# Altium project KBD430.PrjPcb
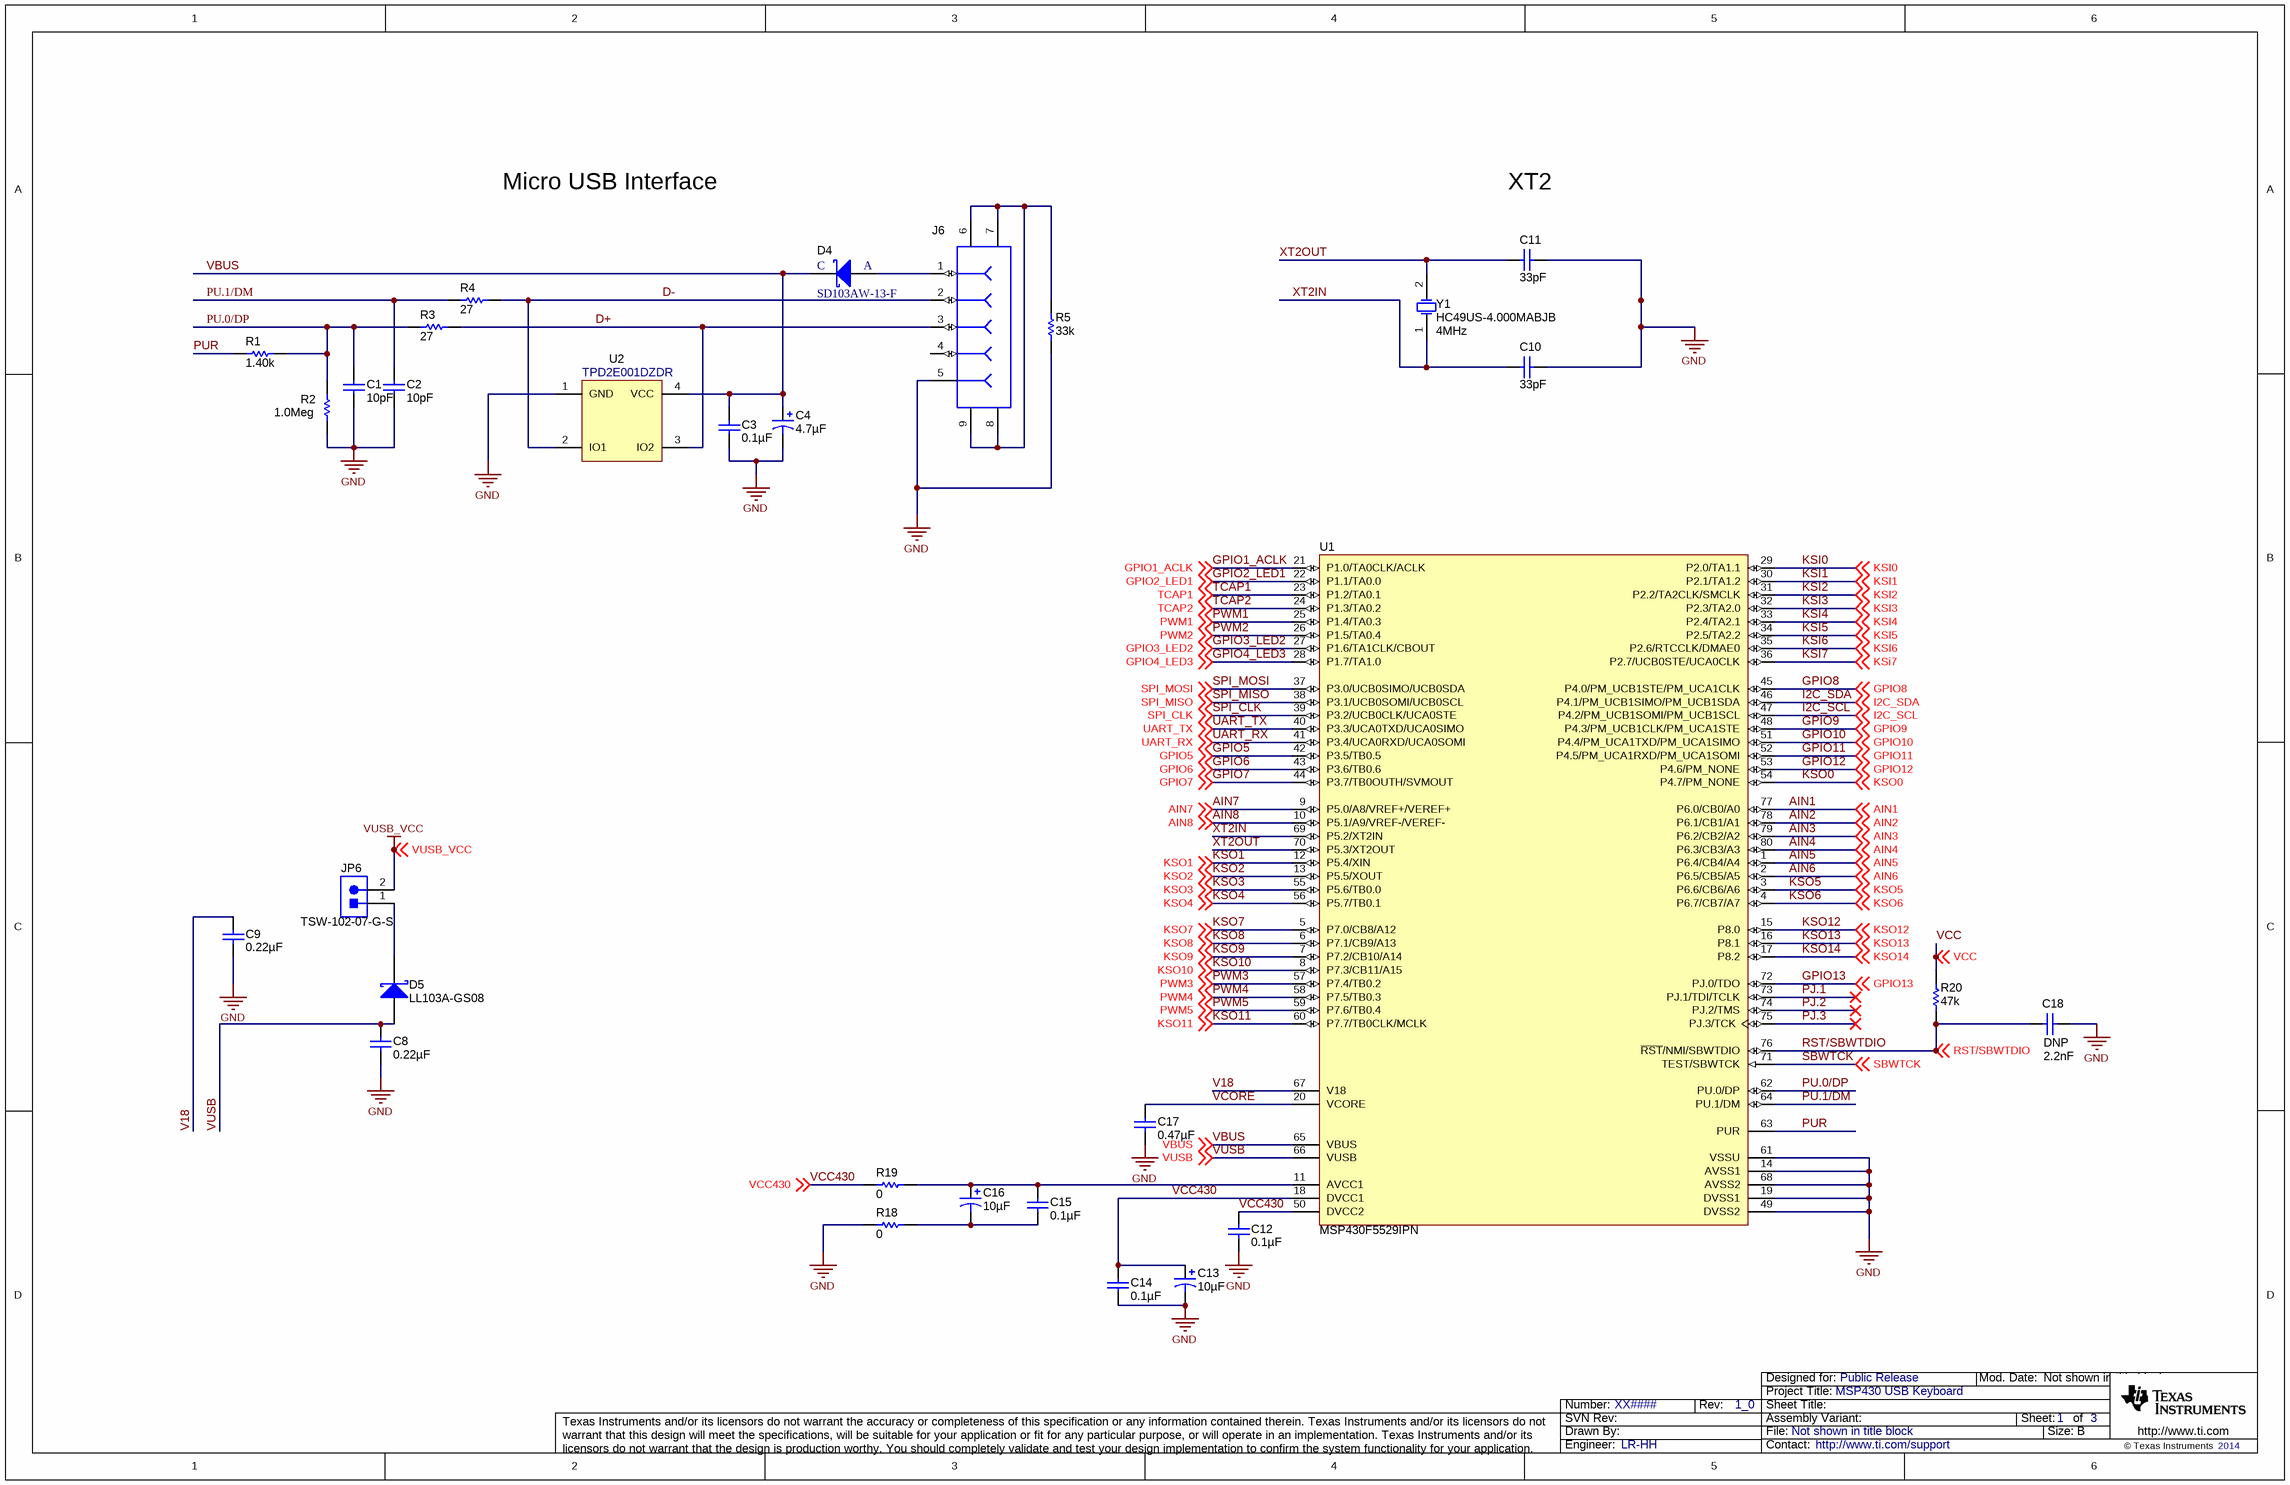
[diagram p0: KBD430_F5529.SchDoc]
CopyrightYear: 2014; PCB_Layout: Hayden Hast; PCB_Rev: 1.0; PRJ_Customer: Public Release; PRJ_Engineer: LR-HH; PRJ_Number: XX####; PRJ_Title: MSP430 USB Keyboard; Project Title: MSP430 USB Keyboard; SCH_Rev: 1_0; TechSupport: http://www.ti.com/support
3 sheets, 72 parts. Net scope: global (net labels, ports and power ports of the same name join across sheets).
Board file: KBD430.PcbDoc
Sheets:
  KBD430_F5529.SchDoc
  KBD430_Shared.SchDoc
  KBD430_G2xx4.SchDoc

## Sheet KBD430_F5529.SchDoc
size 431 x 279 mm; Date: Not shown in title block; ApprovedBy: Not shown in title block; CheckedBy: Not shown in title block; Author: Not shown in title block; CompanyName: Not shown in title block; Engineer: Not shown in title block; Organization: Not shown in title block; Address1: Not shown in title block; Address2: Not shown in title block; Address3: Not shown in title block; Address4: Not shown in title block; DocumentNumber: 1; Revision: Use project parameter SCH_Rev; SheetNumber: 1; SheetTotal: 3; PageSetup: Record=PageOptions|CenterHorizontal=True|CenterVertical=True|PrintScale=0.62|XCorrection=1.00|YCorrection=1.00|PrintKind=0|BorderSize=5000000|LeftOffset=0|BottomOffset=0|Orientation=2|PaperLength=1000|PaperWidth=1000|Scale=100|PaperSource=15|PrintQuality=600|MediaType=1|DitherType=10|PaperKind=Letter (8.5 x 11")|PrintScaleMode=1

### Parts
C1  10pF  [0603]
C2  10pF  [0603]
C3  ValueDisplayed: 0.1µF  [0603]  (hidden comment: 0.1uF)
C4  4.7µF  [3216-18]
C8  ValueDisplayed: 0.22µF  [0603]  (hidden comment: 0.22uF)
C9  ValueDisplayed: 0.22µF  [0603]  (hidden comment: 0.22uF)
C10  33pF  [0603]
C11  33pF  [0603]
C12  ValueDisplayed: 0.1µF  [0603]  (hidden comment: 0.1uF)
C13  ValueDisplayed: 10µF  [3216-18]  (hidden comment: 10uF)
C14  ValueDisplayed: 0.1µF  [0603]  (hidden comment: 0.1uF)
C15  ValueDisplayed: 0.1µF  [0603]  (hidden comment: 0.1uF)
C16  ValueDisplayed: 10µF  [3216-18]  (hidden comment: 10uF)
C17  ValueDisplayed: 0.47µF  [0603]  (hidden comment: 0.47uF)
C18  DNP  ValueDisplayed: 2.2nF  [0603]
D4  SD103AW-13-F  [D_SOD123]
D5  LL103A-GS08  [SOD-80]
J6  ZX62D-AB-5P8  [USB-ZX62D-AB-5P8_REVISED]  (value not drawn)
JP6  TSW-102-07-G-S  [TSW-102-07-G-S]
R1  1.40k  [0603]
R2  1.0Meg  [0603]
R3  27  [0603]
R4  27  [0603]
R5  33k  [0603]
R18  0  [0603]
R19  0  [0603]
R20  47k  [0603]
U1  MSP430F5529IPN  [PN0080A_L]
U2  TPD2E001DZDR  [DZD]
Y1  HC49US-4.000MABJB  Frequency: 4MHz  [Auris_HC49USSMD]

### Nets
GND: C1.2 C2.2 C3.2 C4.2(-) C8.2 C9.2 C10.1 C11.1 C12.2 C13.2(-) C14.2 C17.2 C18.2 J6.5 R2.1 R5.1 R18.1 U1.14(AVSS1) U1.19(DVSS1) U1.49(DVSS2) U1.61(VSSU) U1.68(AVSS2) U2.1(GND)
VCC: R20.2 ; off-sheet VCC
VUSB_VCC: JP6.2 ; off-sheet VUSB_VCC
AIN1: U1.77(P6.0/CB0/A0) ; off-sheet AIN1
AIN2: U1.78(P6.1/CB1/A1) ; off-sheet AIN2
AIN3: U1.79(P6.2/CB2/A2) ; off-sheet AIN3
AIN4: U1.80(P6.3/CB3/A3) ; off-sheet AIN4
AIN5: U1.1(P6.4/CB4/A4) ; off-sheet AIN5
AIN6: U1.2(P6.5/CB5/A5) ; off-sheet AIN6
AIN7: U1.9(P5.0/A8/VREF+/VEREF+) ; off-sheet AIN7
AIN8: U1.10(P5.1/A9/VREF-/VEREF-) ; off-sheet AIN8
D+: J6.3 R3.2 U2.3(IO2)
D-: J6.2 R4.2 U2.2(IO1)
GPIO1_ACLK: U1.21(P1.0/TA0CLK/ACLK) ; off-sheet GPIO1_ACLK
GPIO2_LED1: U1.22(P1.1/TA0.0) ; off-sheet GPIO2_LED1
GPIO3_LED2: U1.27(P1.6/TA1CLK/CBOUT) ; off-sheet GPIO3_LED2
GPIO4_LED3: U1.28(P1.7/TA1.0) ; off-sheet GPIO4_LED3
GPIO5: U1.42(P3.5/TB0.5) ; off-sheet GPIO5
GPIO6: U1.43(P3.6/TB0.6) ; off-sheet GPIO6
GPIO7: U1.44(P3.7/TB0OUTH/SVMOUT) ; off-sheet GPIO7
GPIO8: U1.45(P4.0/PM_UCB1STE/PM_UCA1CLK) ; off-sheet GPIO8
GPIO9: U1.48(P4.3/PM_UCB1CLK/PM_UCA1STE) ; off-sheet GPIO9
GPIO10: U1.51(P4.4/PM_UCA1TXD/PM_UCA1SIMO) ; off-sheet GPIO10
GPIO11: U1.52(P4.5/PM_UCA1RXD/PM_UCA1SOMI) ; off-sheet GPIO11
GPIO12: U1.53(P4.6/PM_NONE) ; off-sheet GPIO12
GPIO13: U1.72(PJ.0/TDO) ; off-sheet GPIO13
I2C_SCL: U1.47(P4.2/PM_UCB1SOMI/PM_UCB1SCL) ; off-sheet I2C_SCL
I2C_SDA: U1.46(P4.1/PM_UCB1SIMO/PM_UCB1SDA) ; off-sheet I2C_SDA
KSI0: U1.29(P2.0/TA1.1) ; off-sheet KSI0
KSI1: U1.30(P2.1/TA1.2) ; off-sheet KSI1
KSI2: U1.31(P2.2/TA2CLK/SMCLK) ; off-sheet KSI2
KSI3: U1.32(P2.3/TA2.0) ; off-sheet KSI3
KSI4: U1.33(P2.4/TA2.1) ; off-sheet KSI4
KSI5: U1.34(P2.5/TA2.2) ; off-sheet KSI5
KSI6: U1.35(P2.6/RTCCLK/DMAE0) ; off-sheet KSI6
KSI7: U1.36(P2.7/UCB0STE/UCA0CLK) ; off-sheet KSi7
KSO0: U1.54(P4.7/PM_NONE) ; off-sheet KSO0
KSO1: U1.12(P5.4/XIN) ; off-sheet KSO1
KSO2: U1.13(P5.5/XOUT) ; off-sheet KSO2
KSO3: U1.55(P5.6/TB0.0) ; off-sheet KSO3
KSO4: U1.56(P5.7/TB0.1) ; off-sheet KSO4
KSO5: U1.3(P6.6/CB6/A6) ; off-sheet KSO5
KSO6: U1.4(P6.7/CB7/A7) ; off-sheet KSO6
KSO7: U1.5(P7.0/CB8/A12) ; off-sheet KSO7
KSO8: U1.6(P7.1/CB9/A13) ; off-sheet KSO8
KSO9: U1.7(P7.2/CB10/A14) ; off-sheet KSO9
KSO10: U1.8(P7.3/CB11/A15) ; off-sheet KSO10
KSO11: U1.60(P7.7/TB0CLK/MCLK) ; off-sheet KSO11
KSO12: U1.15(P8.0) ; off-sheet KSO12
KSO13: U1.16(P8.1) ; off-sheet KSO13
KSO14: U1.17(P8.2) ; off-sheet KSO14
PJ.1: U1.73(PJ.1/TDI/TCLK)
PJ.2: U1.74(PJ.2/TMS)
PJ.3: U1.75(PJ.3/TCK)
PU.0/DP: C1.1 R1.2 R2.2 R3.1 U1.62(PU.0/DP)
PU.1/DM: C2.1 R4.1 U1.64(PU.1/DM)
PUR: R1.1 U1.63(PUR)
PWM1: U1.25(P1.4/TA0.3) ; off-sheet PWM1
PWM2: U1.26(P1.5/TA0.4) ; off-sheet PWM2
PWM3: U1.57(P7.4/TB0.2) ; off-sheet PWM3
PWM4: U1.58(P7.5/TB0.3) ; off-sheet PWM4
PWM5: U1.59(P7.6/TB0.4) ; off-sheet PWM5
RST/SBWTDIO: C18.1 R20.1 U1.76(~{RST}/NMI/SBWTDIO) ; off-sheet RST/SBWTDIO
SBWTCK: U1.71(TEST/SBWTCK) ; off-sheet SBWTCK
SPI_CLK: U1.39(P3.2/UCB0CLK/UCA0STE) ; off-sheet SPI_CLK
SPI_MISO: U1.38(P3.1/UCB0SOMI/UCB0SCL) ; off-sheet SPI_MISO
SPI_MOSI: U1.37(P3.0/UCB0SIMO/UCB0SDA) ; off-sheet SPI_MOSI
TCAP1: U1.23(P1.2/TA0.1) ; off-sheet TCAP1
TCAP2: U1.24(P1.3/TA0.2) ; off-sheet TCAP2
UART_RX: U1.41(P3.4/UCA0RXD/UCA0SOMI) ; off-sheet UART_RX
UART_TX: U1.40(P3.3/UCA0TXD/UCA0SIMO) ; off-sheet UART_TX
V18: C9.1 U1.67(V18)
VBUS: C3.1 C4.1(+) D4.1 U1.65(VBUS) U2.4(VCC) ; off-sheet VBUS
VCC430: C12.1 C13.1(+) C14.1 R19.1 U1.18(DVCC1) U1.50(DVCC2) ; off-sheet VCC430
VCORE: C17.1 U1.20(VCORE)
VUSB: C8.1 D5.2(A) U1.66(VUSB) ; off-sheet VUSB
XT2IN: C10.2 U1.69(P5.2/XT2IN) Y1.1(OSC1)
XT2OUT: C11.2 U1.70(P5.3/XT2OUT) Y1.2(OSC2)
NetC15_1: C15.1 C16.1(+) R19.2 U1.11(AVCC1)
NetC15_2: C15.2 C16.2(-) R18.2
NetD4_2: D4.2 J6.1
NetD5_1: D5.1(K) JP6.1
NetJ6_6: J6.6 J6.7 J6.8 J6.9 R5.2

Not connected (* = marked no-connect by the designer): J6 4

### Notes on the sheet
- Micro USB Interface
- XT2

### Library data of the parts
C1 C2 = C0603C100J5GACTU: CAP, CERM, 10pF, 50V, +/-5%, C0G/NP0, 0603; Manufacturer: Kemet; Polarized: N; CompType: Capacitor; U/M: EA; Cap_F: 0.00000000001; Tolerance_%: 5; Value1: Unknown; VDC_V: 50; TaMin_C: -55; TaMax_C: 125
C3 = C0603C104K5RACTU: CAP, CERM, 0.1uF, 50V, +/-10%, X7R, 0603; Manufacturer: Kemet; Polarized: N; CompType: Capacitor; U/M: EA; Cap_F: 0.0000001; Tolerance_%: 10; Value1: Unknown; VDC_V: 50; TaMin_C: -55; TaMax_C: 125
C4 = 293D475X9010A2TE3: CAP, TA, 4.7uF, 10V, +/-10%, 5 ohm, SMD; Manufacturer: Vishay-Sprague; Polarized: Y; CompType: Capacitor; U/M: EA; Cap_F: 0.0000047; Tolerance_%: 10; Value1: 5 ohm; ESR_Ohm: 5; IRMS_A: 0.12; TaMin_C: -55; TaMax_C: 125; Cap_Case: A
C8 C9 = C1608X7R1C224K: CAP, CERM, 0.22uF, 16V, +/-10%, X7R, 0603; Manufacturer: TDK; Polarized: N; CompType: Capacitor; U/M: EA; Cap_F: 0.00000022; Tolerance_%: 10; ESR_Ohm: 0.0125; Value1: 0.0125 ohm; VDC_V: 16; TaMin_C: -55; TaMax_C: 125
C10 C11 = C1608C0G1H330J: CAP, CERM, 33pF, 50V, +/-5%, C0G/NP0, 0603; Manufacturer: TDK; Polarized: N; CompType: Capacitor; U/M: EA; Cap_F: 0.000000000033; Tolerance_%: 5; ESR_Ohm: 0.2649; Value1: 0.2649 ohm; VDC_V: 50; TaMin_C: -55; TaMax_C: 125
C12 C14 C15 = C0603C104K4RACTU: CAP, CERM, 0.1uF, 16V, +/-10%, X7R, 0603; Manufacturer: Kemet; Polarized: N; CompType: Capacitor; U/M: EA; Cap_F: 0.0000001; Tolerance_%: 10; Value1: Unknown; VDC_V: 16; TaMin_C: -55; TaMax_C: 125
C13 C16 = 293D106X0010A2TE3: CAP, TA, 10uF, 10V, +/-20%, 3.4 ohm, SMD; Manufacturer: Vishay-Sprague; Polarized: Y; CompType: Capacitor; U/M: EA; Cap_F: 0.00001; Tolerance_%: 20; Value1: 3.4 ohm; VDC_V: 10; ESR_Ohm: 3.4; IRMS_A: 0.15; TaMin_C: -55; TaMax_C: 125; Cap_Case: A
C17 = C0603C474K8PACTU: CAP, CERM, 0.47uF, 10V, +/-10%, X5R, 0603; Manufacturer: Kemet; Polarized: N; CompType: Capacitor; U/M: EA; Cap_F: 0.00000047; Tolerance_%: 10; Value1: Unknown; TaMin_C: -55; TaMax_C: 85
C18 = 06031C222JAT2A: CAP, CERM, 2200pF, 100V, +/-5%, X7R, 0603; Manufacturer: AVX; Polarized: N; CompType: Capacitor; U/M: EA; Cap_F: 0.0000000022; Tolerance_%: 5; ESR_Ohm: 0.192; Value1: 0.192 ohm; VDC_V: 100; TaMin_C: -55; TaMax_C: 125
D4 = SD103AW-13-F: DIODE, SCHOTTKY, 0.35A, 40V, SOD-123; MANUFACTURER: DIODES INC; POPULATE: Y; CONSIGNED: N
D5 = LL103A-GS08: Diode, Schottky, 40V, 0.2A, 3.7x1.6x1.6mm; Manufacturer: Vishay-Semiconductor; U/M: EA; Vf_V: 0.6; Value2: 0.6V; Io_A: 0.2; Vr_V: 40; TJmax_C: 125
J6 = ZX62D-AB-5P8: CONNECTOR,  MICRO-USB-AB, RECEPTACLE, RIGHT ANGLE, 5-PIN; MANUFACTURER: HIROSE; POPULATE: Y; CONSIGNED: N
JP6 = TSW-102-07-G-S: Header, 100mil, 2x1, Gold, TH; Manufacturer: Samtec; SymbolCreator: a0412235; U/M: EA
R1 = CRCW06031K40FKEA: RES, 1.40k ohm, 1%, 0.1W, 0603; Manufacturer: Vishay-Dale; CompType: Resistor; Res_ohm: 1400; Value_Code: 1k40; Tolerance_%: 1; Power_W: 0.1; VDC_V: 75; TempCo: 100 ppm/C; EIA_Code: E96; U/M: EA
R2 = CRCW06031M00JNEA: RES, 1.0Meg ohm, 5%, 0.1W, 0603; Manufacturer: Vishay-Dale; CompType: Resistor; Res_ohm: 1000000; Value_Code: 1M00; Tolerance_%: 5; Power_W: 0.1; VDC_V: 75; TempCo: 200 ppm/C; EIA_Code: E24; U/M: EA
R3 R4 = CRCW060327R0JNEA: RES, 27 ohm, 5%, 0.1W, 0603; Manufacturer: Vishay-Dale; CompType: Resistor; Value_Code: 27R0; Tolerance_%: 5; Power_W: 0.1; VDC_V: 75; TempCo: 200 ppm/C; EIA_Code: E24; U/M: EA
R5 = CRCW060333K0JNEA: RES, 33k ohm, 5%, 0.1W, 0603; Manufacturer: Vishay-Dale; CompType: Resistor; Res_ohm: 33000; Value_Code: 33k0; Tolerance_%: 5; Power_W: 0.1; VDC_V: 75; TempCo: 200 ppm/C; EIA_Code: E24; U/M: EA
R18 R19 = CRCW06030000Z0EA: RES, 0 ohm, 5%, 0.1W, 0603; Manufacturer: Vishay-Dale; CompType: Resistor; Value_Code: 0000; Tolerance_%: 5; Power_W: 0.1; VDC_V: 75; TempCo: 200 ppm/C; EIA_Code: E24; U/M: EA
R20 = CRCW060347K0JNEA: RES, 47k ohm, 5%, 0.1W, 0603; Manufacturer: Vishay-Dale; CompType: Resistor; Res_ohm: 47000; Value_Code: 47k0; Tolerance_%: 5; Power_W: 0.1; VDC_V: 75; TempCo: 200 ppm/C; EIA_Code: E24; U/M: EA
U1 = MSP430F5529IPN: Mixed Signal MicroController, PN0080A; Alternate Manufacturer: None; Manufacturer: Texas Instruments; ADC: 12-bit SAR; ADC Channels: 16; Brown Out Reset: Yes; DMA: 3; Eco-Plan: Green (RoHS & no Sb/Br); Flash(KB): 128; Frequency(MHz): 25; GPIO: 63; Multiplier: 32x32; SRAM(B): 8192; SubFamily: 5 Series; Timers - 16-bit: 4; USB: 1; USCI_A (UART/LIN/IrDA/SPI): 2; SymbolCreator: Altium/a0412235; CompType: IC; U/M: EA
U2 = TPD2E001DZDR: IC, LOW-CAPACITANCE 2-Chan ±15-kV ESD-PROTECTION ARRAY, SOP-4; MANUFACTURER: TEXAS INSTRUMENTS; POPULATE: Y
Y1 = Q-4M-HC49USSMD-F-30-50-E-30-TR: Crystal, 4MHz, 30pF, SMD; Manufacturer: Auris-GmbH; SymbolCreator: a0412235; U/M: EA; TaMin_C: -40; TaMax_C: 85; Frequency Stability: ±50ppm

## Sheet KBD430_Shared.SchDoc
size 431 x 279 mm; Date: Not shown in title block; ApprovedBy: Not shown in title block; CheckedBy: Not shown in title block; Author: Not shown in title block; CompanyName: Not shown in title block; Engineer: Not shown in title block; Organization: Not shown in title block; Address1: Not shown in title block; Address2: Not shown in title block; Address3: Not shown in title block; Address4: Not shown in title block; DocumentNumber: 1; Revision: Use project parameter SCH_Rev; SheetNumber: 2; SheetTotal: 3; PageSetup: Record=PageOptions|CenterHorizontal=True|CenterVertical=True|PrintScale=0.62|XCorrection=1.00|YCorrection=1.00|PrintKind=0|BorderSize=5000000|LeftOffset=0|BottomOffset=0|Orientation=2|PaperLength=1000|PaperWidth=1000|Scale=100|PaperSource=15|PrintQuality=600|MediaType=1|DitherType=10|PaperKind=Letter (8.5 x 11")|PrintScaleMode=1
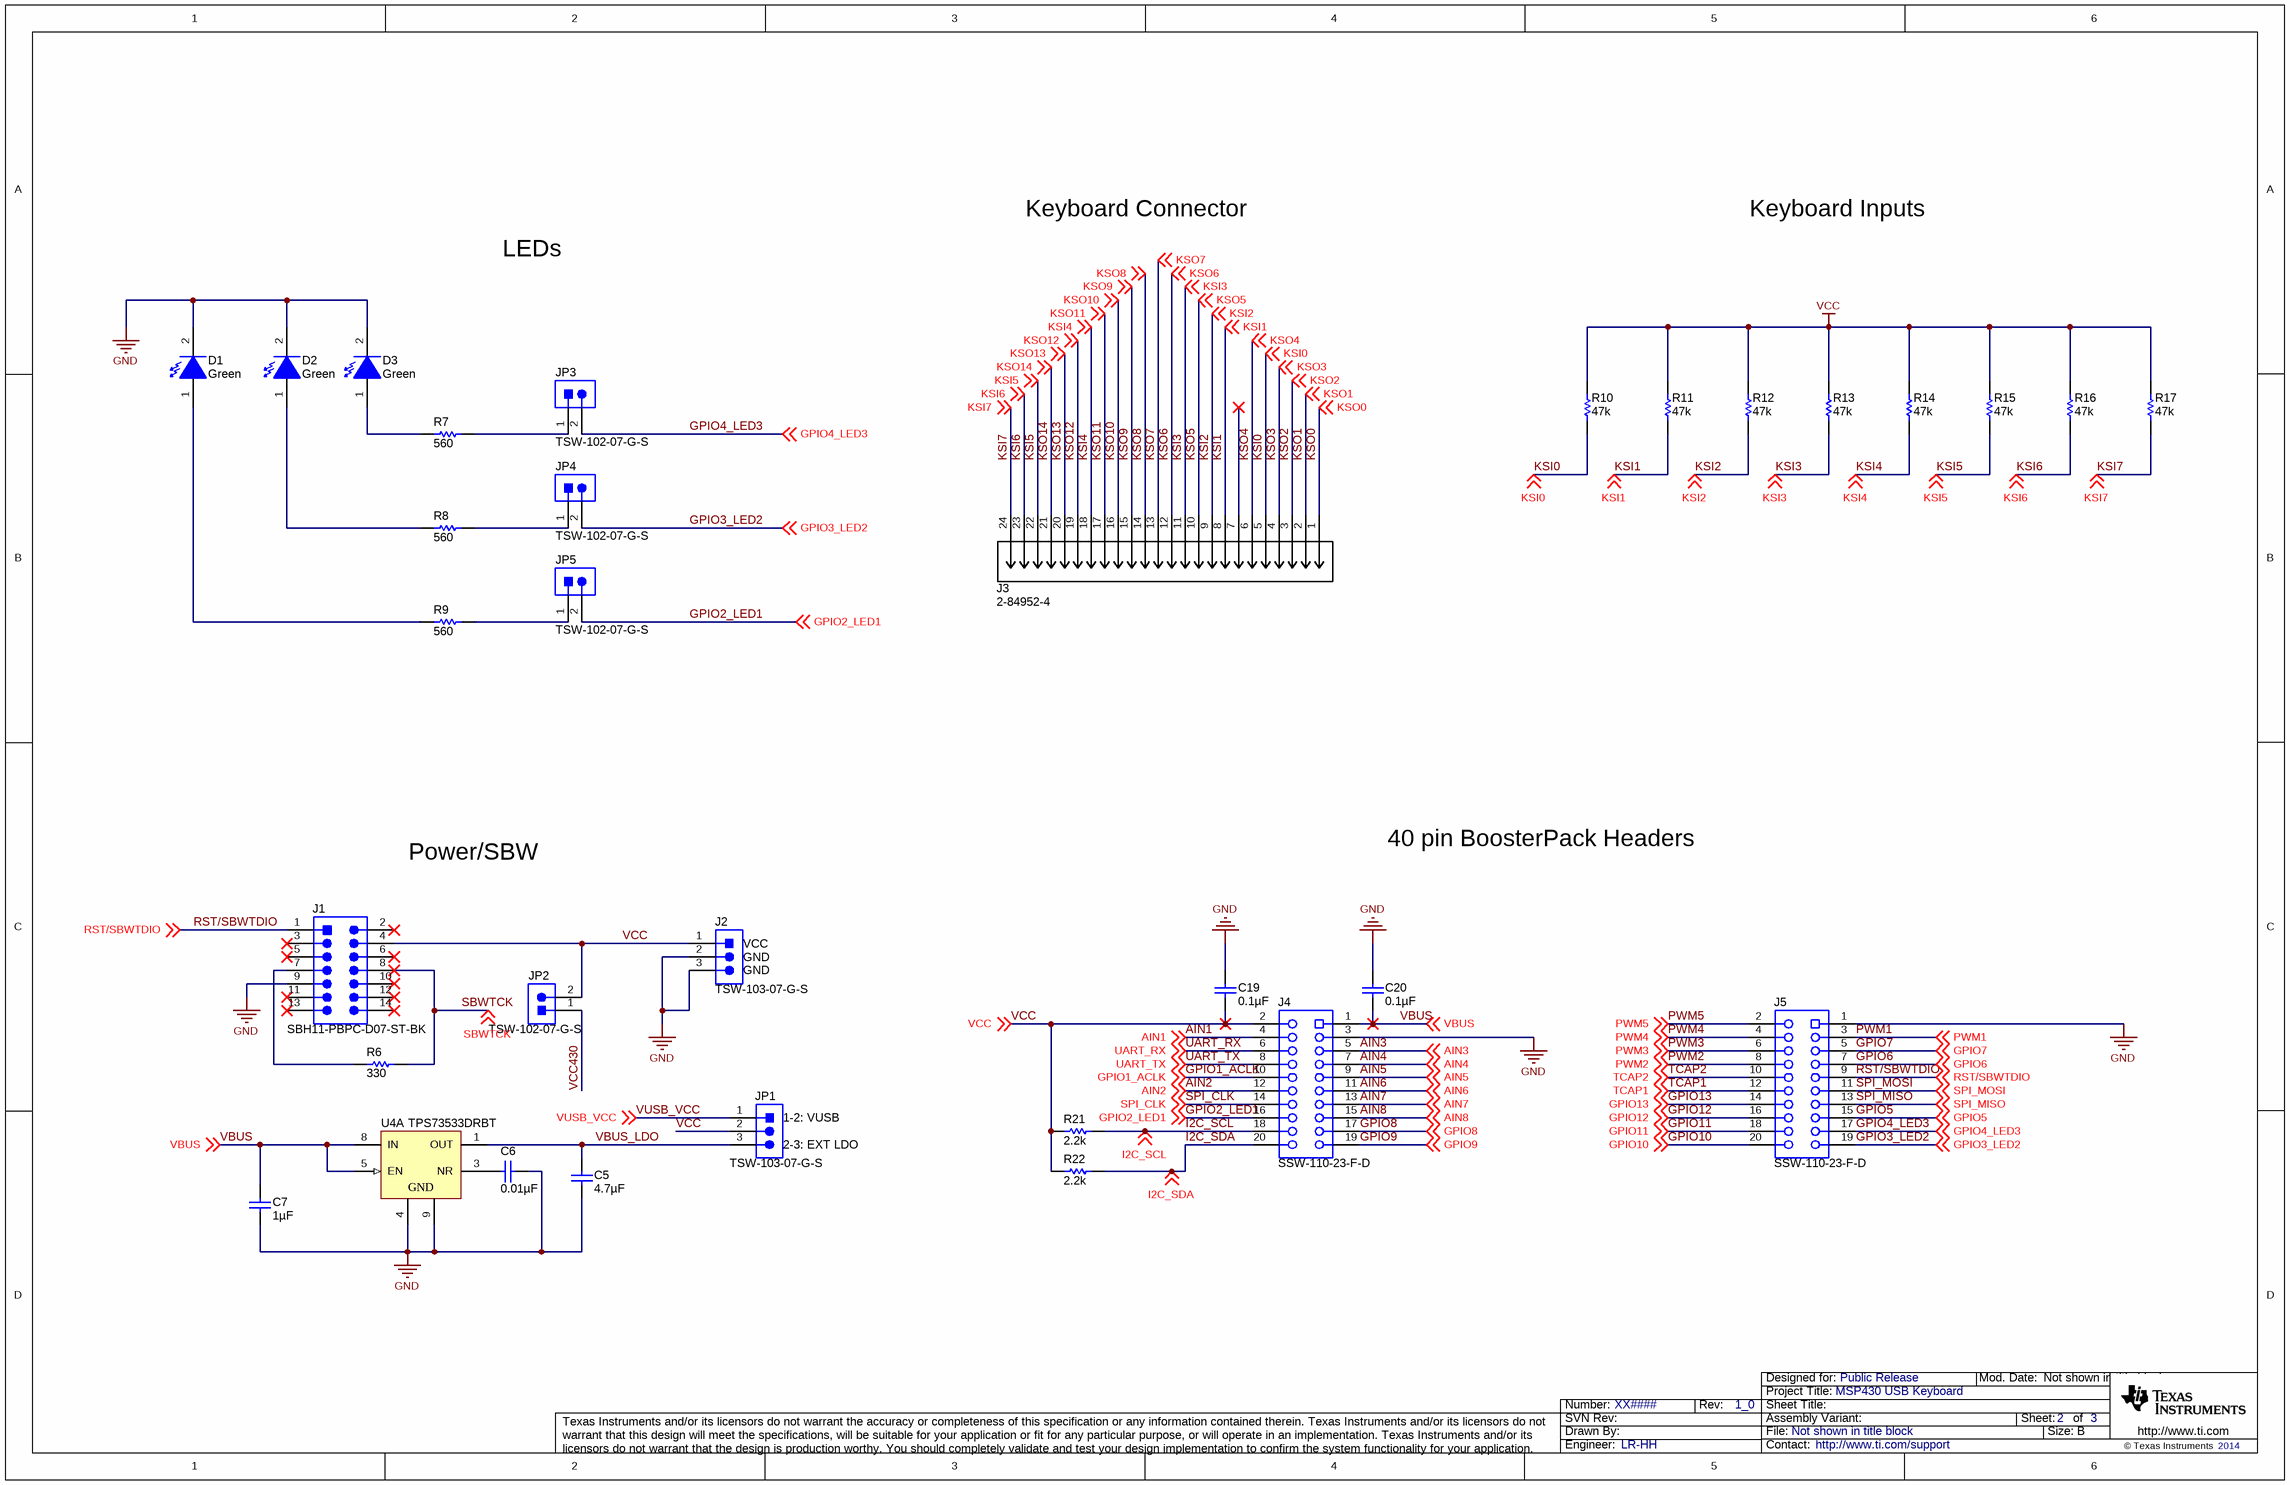
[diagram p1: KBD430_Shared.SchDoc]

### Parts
C5  ValueDisplayed: 4.7µF  [0603]  (hidden comment: 4.7uF)
C6  ValueDisplayed: 0.01µF  [0603]  (hidden comment: 0.01uF)
C7  ValueDisplayed: 1µF  [0603]  (hidden comment: 1uF)
C19  ValueDisplayed: 0.1µF  [0603]  (hidden comment: 0.1uF)
C20  ValueDisplayed: 0.1µF  [0603]  (hidden comment: 0.1uF)
D1  value Green  [LED_LTST-C171]  (hidden comment: LTST-C171GKT)
D2  value Green  [LED_LTST-C171]  (hidden comment: LTST-C171GKT)
D3  value Green  [LED_LTST-C171]  (hidden comment: LTST-C171GKT)
J1  SBH11-PBPC-D07-ST-BK  [CONN_SBH11-PBPC-D07-ST-BK]
J2  TSW-103-07-G-S  [TSW-103-07-G-S]
J3  2-84952-4  [CON24_SMT-RA_FCC]
J4  SSW-110-23-F-D  [CONN_SSW-110-23-F-D]
J5  SSW-110-23-F-D  [CONN_SSW-110-23-F-D]
JP1  TSW-103-07-G-S  [TSW-103-07-G-S]
JP2  TSW-102-07-G-S  [TSW-102-07-G-S]
JP3  TSW-102-07-G-S  [TSW-102-07-G-S]
JP4  TSW-102-07-G-S  [TSW-102-07-G-S]
JP5  TSW-102-07-G-S  [TSW-102-07-G-S]
R6  330  [0603]
R7  560  [0603]
R8  560  [0603]
R9  560  [0603]
R10  47k  [0603]
R11  47k  [0603]
R12  47k  [0603]
R13  47k  [0603]
R14  47k  [0603]
R15  47k  [0603]
R16  47k  [0603]
R17  47k  [0603]
R21  2.2k  [0603]
R22  2.2k  [0603]
U4  TPS73533DRBT  [DRB8_1P75X1P5]  (part A of 2)

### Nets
GND: C5.2 C6.1 C7.2 C19.1 C20.1 D1.2(K) D2.2(K) D3.2(K) J1.9 J2.2 J2.3 J4.3 J5.1 U4.4(GND) U4.9(GND)
VCC: C19.2 J1.4 J2.1 J4.2 JP1.2 JP2.2 R10.2 R11.2 R12.2 R13.2 R14.2 R15.2 R16.2 R17.2 R21.1 R22.1 ; off-sheet VCC
VUSB_VCC: JP1.1 ; off-sheet VUSB_VCC
AIN1: J4.4 ; off-sheet AIN1
AIN2: J4.12 ; off-sheet AIN2
AIN3: J4.5 ; off-sheet AIN3
AIN4: J4.7 ; off-sheet AIN4
AIN5: J4.9 ; off-sheet AIN5
AIN6: J4.11 ; off-sheet AIN6
AIN7: J4.13 ; off-sheet AIN7
AIN8: J4.15 ; off-sheet AIN8
GPIO1_ACLK: J4.10 ; off-sheet GPIO1_ACLK
GPIO2_LED1: J4.16 JP5.2 ; off-sheet GPIO2_LED1
GPIO3_LED2: J5.19 JP4.2 ; off-sheet GPIO3_LED2
GPIO4_LED3: J5.17 JP3.2 ; off-sheet GPIO4_LED3
GPIO5: J5.15 ; off-sheet GPIO5
GPIO6: J5.7 ; off-sheet GPIO6
GPIO7: J5.5 ; off-sheet GPIO7
GPIO8: J4.17 ; off-sheet GPIO8
GPIO9: J4.19 ; off-sheet GPIO9
GPIO10: J5.20 ; off-sheet GPIO10
GPIO11: J5.18 ; off-sheet GPIO11
GPIO12: J5.16 ; off-sheet GPIO12
GPIO13: J5.14 ; off-sheet GPIO13
I2C_SCL: J4.18 R21.2 ; off-sheet I2C_SCL
I2C_SDA: J4.20 R22.2 ; off-sheet I2C_SDA
KSI0: J3.5 R10.1 ; off-sheet KSI0
KSI1: J3.8 R11.1 ; off-sheet KSI1
KSI2: J3.9 R12.1 ; off-sheet KSI2
KSI3: J3.11 R13.1 ; off-sheet KSI3
KSI4: J3.18 R14.1 ; off-sheet KSI4
KSI5: J3.22 R15.1 ; off-sheet KSI5
KSI6: J3.23 R16.1 ; off-sheet KSI6
KSI7: J3.24 R17.1 ; off-sheet KSI7
KSO0: J3.1 ; off-sheet KSO0
KSO1: J3.2 ; off-sheet KSO1
KSO2: J3.3 ; off-sheet KSO2
KSO3: J3.4 ; off-sheet KSO3
KSO4: J3.6 ; off-sheet KSO4
KSO5: J3.10 ; off-sheet KSO5
KSO6: J3.12 ; off-sheet KSO6
KSO7: J3.13 ; off-sheet KSO7
KSO8: J3.14 ; off-sheet KSO8
KSO9: J3.15 ; off-sheet KSO9
KSO10: J3.16 ; off-sheet KSO10
KSO11: J3.17 ; off-sheet KSO11
KSO12: J3.19 ; off-sheet KSO12
KSO13: J3.20 ; off-sheet KSO13
KSO14: J3.21 ; off-sheet KSO14
PWM1: J5.3 ; off-sheet PWM1
PWM2: J5.8 ; off-sheet PWM2
PWM3: J5.6 ; off-sheet PWM3
PWM4: J5.4 ; off-sheet PWM4
PWM5: J5.2 ; off-sheet PWM5
RST/SBWTDIO: J1.1 J5.9 ; off-sheet RST/SBWTDIO
SBWTCK: J1.8 R6.2 ; off-sheet SBWTCK
SPI_CLK: J4.14 ; off-sheet SPI_CLK
SPI_MISO: J5.13 ; off-sheet SPI_MISO
SPI_MOSI: J5.11 ; off-sheet SPI_MOSI
TCAP1: J5.12 ; off-sheet TCAP1
TCAP2: J5.10 ; off-sheet TCAP2
UART_RX: J4.6 ; off-sheet UART_RX
UART_TX: J4.8 ; off-sheet UART_TX
VBUS: C7.1 C20.2 J4.1 U4.5(EN) U4.8(IN) ; off-sheet VBUS
VBUS_LDO: C5.1 JP1.3 U4.1(OUT)
VCC430: JP2.1
NetC6_2: C6.2 U4.3(NR)
NetD1_1: D1.1(A) R9.1
NetD2_1: D2.1(A) R8.1
NetD3_1: D3.1(A) R7.1
NetJ1_7: J1.7 R6.1
NetJP3_1: JP3.1 R7.2
NetJP4_1: JP4.1 R8.2
NetJP5_1: JP5.1 R9.2

Not connected (* = marked no-connect by the designer): J1 2* 3* 5* 6* 10* 11* 12* 13* 14*; J3 7*

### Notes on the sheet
- Keyboard Connector
- Keyboard Inputs
- LEDs
- Power/SBW
- 40 pin BoosterPack Headers
- (near J2) VCC
- (near J2) GND
- (near JP1) 1-2: VUSB
- (near JP1) 2-3: EXT LDO

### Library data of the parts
C5 = C0603C475K8PACTU: CAP, CERM, 4.7uF, 10V, +/-10%, X5R, 0603; Manufacturer: Kemet; Polarized: N; CompType: Capacitor; U/M: EA; Cap_F: 0.0000047; Tolerance_%: 10; ESR_Ohm: 0.006; Value1: 0.006 ohm; IRMS_A: 7.24; TaMin_C: -55; TaMax_C: 85
C6 = GRM188R71H103KA01D: CAP, CERM, 0.01uF, 50V, +/-10%, X7R, 0603; Manufacturer: MuRata; Polarized: N; CompType: Capacitor; U/M: EA; Cap_F: 0.00000001; Tolerance_%: 10; Value1: Unknown; VDC_V: 50; TaMin_C: -55; TaMax_C: 125
C7 = C0603C105K4PACTU: CAP, CERM, 1uF, 16V, +/-10%, X5R, 0603; Manufacturer: Kemet; Polarized: N; CompType: Capacitor; U/M: EA; Cap_F: 0.000001; Tolerance_%: 10; Value1: Unknown; VDC_V: 16; TaMin_C: -55; TaMax_C: 85
C19 C20 = 0603YC104JAT2A: CAP, CERM, 0.1uF, 16V, +/-5%, X7R, 0603; Manufacturer: AVX; Polarized: N; CompType: Capacitor; U/M: EA; Cap_F: 0.0000001; Tolerance_%: 5; ESR_Ohm: 0.039; Value1: 0.039 ohm; VDC_V: 16; TaMin_C: -55; TaMax_C: 125
D1-D3 = LTST-C171GKT: LED, Green, SMD; Manufacturer: Lite-On; Type: AlInGaP; Vf_V: 2.1; Value2: 2.1V; Io_A: 20; Value1: W; U/M: EA
J1 = SBH11-PBPC-D07-ST-BK: Header (shrouded), 100 mil, 7x2, Gold, TH; Manufacturer: Sullins Connector Solutions; SymbolCreator: a0412235; U/M: EA
J2 JP1 = TSW-103-07-G-S: Header, 100mil, 3x1, Gold, TH; Manufacturer: Samtec; SymbolCreator: a0799628; U/M: EA
J3 = 2-84952-4: CONN FPC 24POS 1MM RT ANG SMD; Manufacturer_Name: Tyco Electronics Amp; Vendor: Tyco Electronics; Supersection: Connectors; Section: General Purpose
J4 J5 = SSW-110-23-F-D: Connector, Receptacle, 100mil, 10x2, Gold plated, TH; Manufacturer: Samtec; SymbolCreator: a0412235; U/M: EA
JP2-JP5 = TSW-102-07-G-S: as JP6 on sheet KBD430_F5529
R6 = CRCW0603330RJNEA: RES, 330 ohm, 5%, 0.1W, 0603; Manufacturer: Vishay-Dale; CompType: Resistor; Value_Code: 330R; Tolerance_%: 5; Power_W: 0.1; VDC_V: 75; TempCo: 200 ppm/C; EIA_Code: E24; U/M: EA
R7-R9 = CRCW0603560RJNEA: RES, 560 ohm, 5%, 0.1W, 0603; Manufacturer: Vishay-Dale; CompType: Resistor; Value_Code: 560R; Tolerance_%: 5; Power_W: 0.1; VDC_V: 75; TempCo: 200 ppm/C; EIA_Code: E24; U/M: EA
R10-R17 = CRCW060347K0JNEA: as R20 on sheet KBD430_F5529
R21 R22 = CRCW06032K20JNEA: RES, 2.2k ohm, 5%, 0.1W, 0603; Manufacturer: Vishay-Dale; CompType: Resistor; Res_ohm: 2200; Value_Code: 2k20; Tolerance_%: 5; Power_W: 0.1; VDC_V: 75; TempCo: 200 ppm/C; EIA_Code: E24; U/M: EA
U4 = TPS73533DRBT: Single Output High PSRR LDO, 500 mA, Fixed 3.3 V Output, 2.7 to 6.5 V Input, with Low IQ, 8-pin SON (DRB), -40 to 125 degC, Green (RoHS & no Sb/Br); Manufacturer: Texas Instruments; Alternate Manufacturer: None; Alternate PartNumber: Equivalent; Accuracy(%): 2; Fixed Output Options(V): 3.3; Iout(Max)(A): 0.5; Iq(Typ)(mA): 0.04; SubFamily: Single Channel LDO; Vdo(Typ)(mV): 280; Vin(Max)(V): 6.5; Vin(Min)(V): 2.7

## Sheet KBD430_G2xx4.SchDoc
size 431 x 279 mm; Date: Not shown in title block; ApprovedBy: Not shown in title block; CheckedBy: Not shown in title block; Author: Not shown in title block; CompanyName: Not shown in title block; Engineer: Not shown in title block; Organization: Not shown in title block; Address1: Not shown in title block; Address2: Not shown in title block; Address3: Not shown in title block; Address4: Not shown in title block; DocumentNumber: 1; Revision: Use project parameter SCH_Rev; SheetNumber: 3; SheetTotal: 3; PageSetup: Record=PageOptions|CenterHorizontal=True|CenterVertical=True|PrintScale=0.62|XCorrection=1.00|YCorrection=1.00|PrintKind=0|BorderSize=5000000|LeftOffset=0|BottomOffset=0|Orientation=2|PaperLength=1000|PaperWidth=1000|Scale=100|PaperSource=15|PrintQuality=600|MediaType=1|DitherType=10|PaperKind=Letter (8.5 x 11")|PrintScaleMode=1
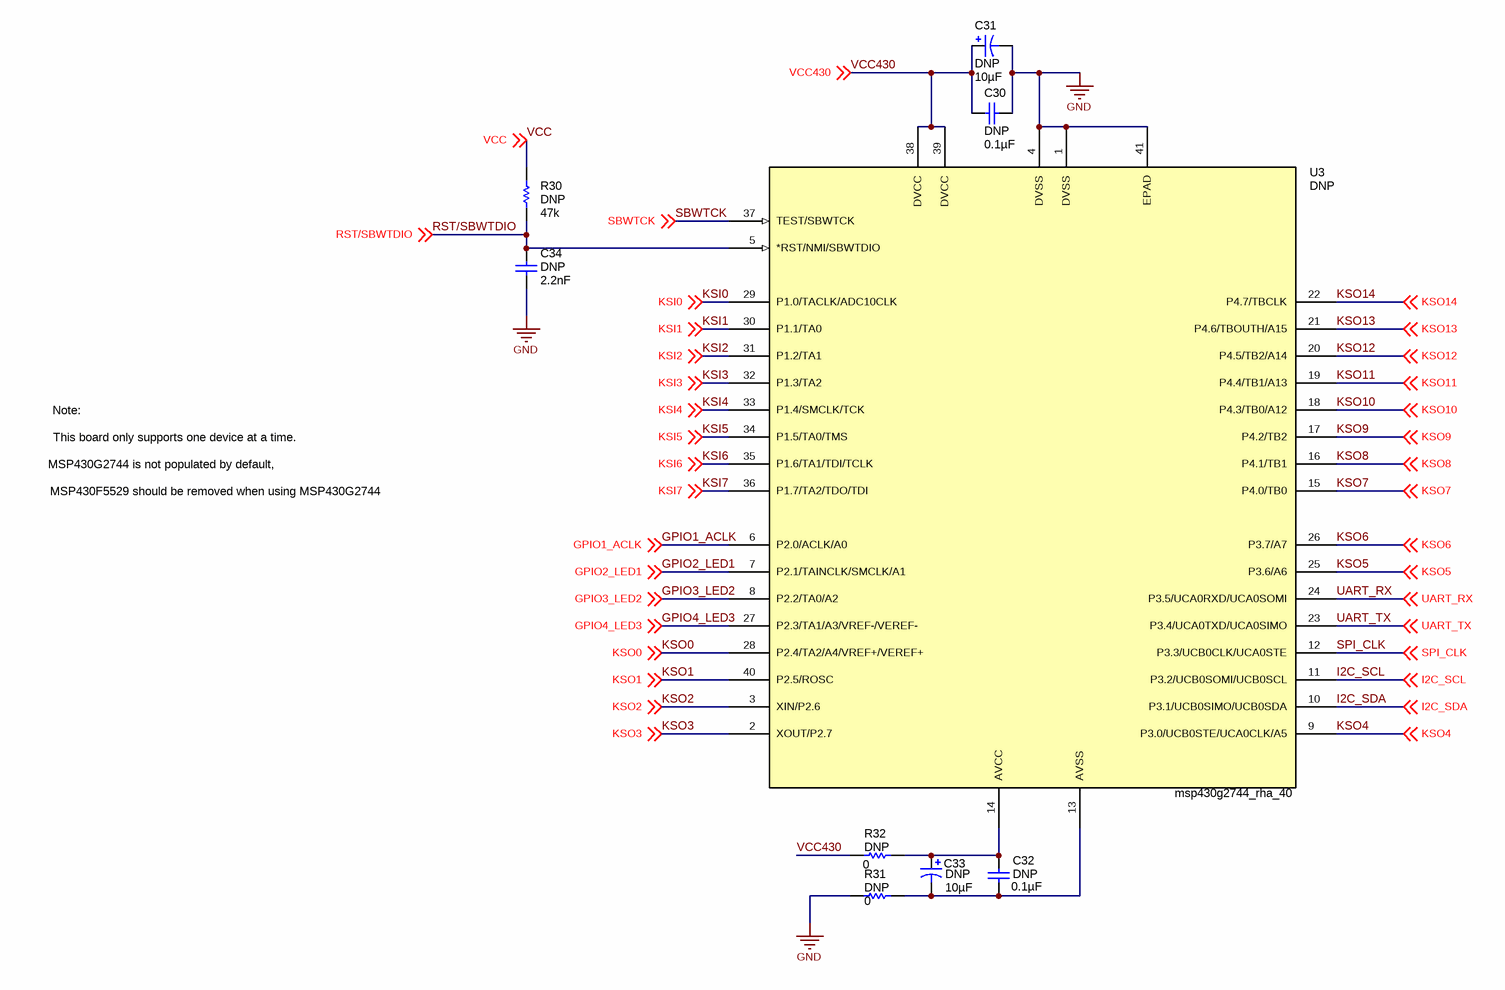
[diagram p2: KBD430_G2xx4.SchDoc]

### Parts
C30  DNP  ValueDisplayed: 0.1µF  [0603]
C31  DNP  ValueDisplayed: 10µF  [3216-18]
C32  DNP  ValueDisplayed: 0.1µF  [0603]
C33  DNP  ValueDisplayed: 10µF  [3216-18]
C34  DNP  ValueDisplayed: 2.2nF  [0603]
R30  DNP  value 47k  [0603]
R31  DNP  value 0  [0603]
R32  DNP  value 0  [0603]
U3  DNP  Manufacturer_Part_Number: msp430g2744_rha_40  [QFN50P600X600X100-40N]

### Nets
GND: C30.2 C31.2(-) C34.2 R31.1 U3.1(DVSS) U3.4(DVSS) U3.41(EPAD)
VCC: R30.2 ; off-sheet VCC
GPIO1_ACLK: U3.6(P2.0/ACLK/A0) ; off-sheet GPIO1_ACLK
GPIO2_LED1: U3.7(P2.1/TAINCLK/SMCLK/A1) ; off-sheet GPIO2_LED1
GPIO3_LED2: U3.8(P2.2/TA0/A2) ; off-sheet GPIO3_LED2
GPIO4_LED3: U3.27(P2.3/TA1/A3/VREF-/VEREF-) ; off-sheet GPIO4_LED3
I2C_SCL: U3.11(P3.2/UCB0SOMI/UCB0SCL) ; off-sheet I2C_SCL
I2C_SDA: U3.10(P3.1/UCB0SIMO/UCB0SDA) ; off-sheet I2C_SDA
KSI0: U3.29(P1.0/TACLK/ADC10CLK) ; off-sheet KSI0
KSI1: U3.30(P1.1/TA0) ; off-sheet KSI1
KSI2: U3.31(P1.2/TA1) ; off-sheet KSI2
KSI3: U3.32(P1.3/TA2) ; off-sheet KSI3
KSI4: U3.33(P1.4/SMCLK/TCK) ; off-sheet KSI4
KSI5: U3.34(P1.5/TA0/TMS) ; off-sheet KSI5
KSI6: U3.35(P1.6/TA1/TDI/TCLK) ; off-sheet KSI6
KSI7: U3.36(P1.7/TA2/TDO/TDI) ; off-sheet KSI7
KSO0: U3.28(P2.4/TA2/A4/VREF+/VEREF+) ; off-sheet KSO0
KSO1: U3.40(P2.5/ROSC) ; off-sheet KSO1
KSO2: U3.3(XIN/P2.6) ; off-sheet KSO2
KSO3: U3.2(XOUT/P2.7) ; off-sheet KSO3
KSO4: U3.9(P3.0/UCB0STE/UCA0CLK/A5) ; off-sheet KSO4
KSO5: U3.25(P3.6/A6) ; off-sheet KSO5
KSO6: U3.26(P3.7/A7) ; off-sheet KSO6
KSO7: U3.15(P4.0/TB0) ; off-sheet KSO7
KSO8: U3.16(P4.1/TB1) ; off-sheet KSO8
KSO9: U3.17(P4.2/TB2) ; off-sheet KSO9
KSO10: U3.18(P4.3/TB0/A12) ; off-sheet KSO10
KSO11: U3.19(P4.4/TB1/A13) ; off-sheet KSO11
KSO12: U3.20(P4.5/TB2/A14) ; off-sheet KSO12
KSO13: U3.21(P4.6/TBOUTH/A15) ; off-sheet KSO13
KSO14: U3.22(P4.7/TBCLK) ; off-sheet KSO14
RST/SBWTDIO: C34.1 R30.1 U3.5(*RST/NMI/SBWTDIO) ; off-sheet RST/SBWTDIO
SBWTCK: U3.37(TEST/SBWTCK) ; off-sheet SBWTCK
SPI_CLK: U3.12(P3.3/UCB0CLK/UCA0STE) ; off-sheet SPI_CLK
UART_RX: U3.24(P3.5/UCA0RXD/UCA0SOMI) ; off-sheet UART_RX
UART_TX: U3.23(P3.4/UCA0TXD/UCA0SIMO) ; off-sheet UART_TX
VCC430: C30.1 C31.1(+) R32.1 U3.38(DVCC) U3.39(DVCC) ; off-sheet VCC430
NetC32_1: C32.1 C33.1(+) R32.2 U3.14(AVCC)
NetC32_2: C32.2 C33.2(-) R31.2 U3.13(AVSS)

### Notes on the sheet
- Note:
- MSP430G2744 is not populated by default,
- This board only supports one device at a time.
- MSP430F5529 should be removed when using MSP430G2744

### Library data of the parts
C30 C32 = C0603C104K4RACTU: as C12 on sheet KBD430_F5529
C31 C33 = 293D106X0010A2TE3: as C13 on sheet KBD430_F5529
C34 = 06031C222JAT2A: as C18 on sheet KBD430_F5529
R30 = CRCW060347K0JNEA: as R20 on sheet KBD430_F5529
R31 R32 = CRCW06030000Z0EA: as R18 on sheet KBD430_F5529
U3 = MSP430G2744_RHA_: MSP430G2744, VQFN40; Vendor: TEXAS INSTRUMENTS

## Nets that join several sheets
GND: KBD430_F5529 (23 pins), KBD430_Shared (15 pins), KBD430_G2xx4 (7 pins)
VCC: KBD430_F5529 (R20.2), KBD430_Shared (16 pins), KBD430_G2xx4 (R30.2)
VUSB_VCC: KBD430_F5529 (JP6.2), KBD430_Shared (JP1.1)
AIN1: KBD430_F5529 (U1.77), KBD430_Shared (J4.4)
AIN2: KBD430_F5529 (U1.78), KBD430_Shared (J4.12)
AIN3: KBD430_F5529 (U1.79), KBD430_Shared (J4.5)
AIN4: KBD430_F5529 (U1.80), KBD430_Shared (J4.7)
AIN5: KBD430_F5529 (U1.1), KBD430_Shared (J4.9)
AIN6: KBD430_F5529 (U1.2), KBD430_Shared (J4.11)
AIN7: KBD430_F5529 (U1.9), KBD430_Shared (J4.13)
AIN8: KBD430_F5529 (U1.10), KBD430_Shared (J4.15)
GPIO1_ACLK: KBD430_F5529 (U1.21), KBD430_Shared (J4.10), KBD430_G2xx4 (U3.6)
GPIO2_LED1: KBD430_F5529 (U1.22), KBD430_Shared (J4.16 JP5.2), KBD430_G2xx4 (U3.7)
GPIO3_LED2: KBD430_F5529 (U1.27), KBD430_Shared (J5.19 JP4.2), KBD430_G2xx4 (U3.8)
GPIO4_LED3: KBD430_F5529 (U1.28), KBD430_Shared (J5.17 JP3.2), KBD430_G2xx4 (U3.27)
GPIO5: KBD430_F5529 (U1.42), KBD430_Shared (J5.15)
GPIO6: KBD430_F5529 (U1.43), KBD430_Shared (J5.7)
GPIO7: KBD430_F5529 (U1.44), KBD430_Shared (J5.5)
GPIO8: KBD430_F5529 (U1.45), KBD430_Shared (J4.17)
GPIO9: KBD430_F5529 (U1.48), KBD430_Shared (J4.19)
GPIO10: KBD430_F5529 (U1.51), KBD430_Shared (J5.20)
GPIO11: KBD430_F5529 (U1.52), KBD430_Shared (J5.18)
GPIO12: KBD430_F5529 (U1.53), KBD430_Shared (J5.16)
GPIO13: KBD430_F5529 (U1.72), KBD430_Shared (J5.14)
I2C_SCL: KBD430_F5529 (U1.47), KBD430_Shared (J4.18 R21.2), KBD430_G2xx4 (U3.11)
I2C_SDA: KBD430_F5529 (U1.46), KBD430_Shared (J4.20 R22.2), KBD430_G2xx4 (U3.10)
KSI0: KBD430_F5529 (U1.29), KBD430_Shared (J3.5 R10.1), KBD430_G2xx4 (U3.29)
KSI1: KBD430_F5529 (U1.30), KBD430_Shared (J3.8 R11.1), KBD430_G2xx4 (U3.30)
KSI2: KBD430_F5529 (U1.31), KBD430_Shared (J3.9 R12.1), KBD430_G2xx4 (U3.31)
KSI3: KBD430_F5529 (U1.32), KBD430_Shared (J3.11 R13.1), KBD430_G2xx4 (U3.32)
KSI4: KBD430_F5529 (U1.33), KBD430_Shared (J3.18 R14.1), KBD430_G2xx4 (U3.33)
KSI5: KBD430_F5529 (U1.34), KBD430_Shared (J3.22 R15.1), KBD430_G2xx4 (U3.34)
KSI6: KBD430_F5529 (U1.35), KBD430_Shared (J3.23 R16.1), KBD430_G2xx4 (U3.35)
KSI7: KBD430_F5529 (U1.36), KBD430_Shared (J3.24 R17.1), KBD430_G2xx4 (U3.36)
KSO0: KBD430_F5529 (U1.54), KBD430_Shared (J3.1), KBD430_G2xx4 (U3.28)
KSO1: KBD430_F5529 (U1.12), KBD430_Shared (J3.2), KBD430_G2xx4 (U3.40)
KSO2: KBD430_F5529 (U1.13), KBD430_Shared (J3.3), KBD430_G2xx4 (U3.3)
KSO3: KBD430_F5529 (U1.55), KBD430_Shared (J3.4), KBD430_G2xx4 (U3.2)
KSO4: KBD430_F5529 (U1.56), KBD430_Shared (J3.6), KBD430_G2xx4 (U3.9)
KSO5: KBD430_F5529 (U1.3), KBD430_Shared (J3.10), KBD430_G2xx4 (U3.25)
KSO6: KBD430_F5529 (U1.4), KBD430_Shared (J3.12), KBD430_G2xx4 (U3.26)
KSO7: KBD430_F5529 (U1.5), KBD430_Shared (J3.13), KBD430_G2xx4 (U3.15)
KSO8: KBD430_F5529 (U1.6), KBD430_Shared (J3.14), KBD430_G2xx4 (U3.16)
KSO9: KBD430_F5529 (U1.7), KBD430_Shared (J3.15), KBD430_G2xx4 (U3.17)
KSO10: KBD430_F5529 (U1.8), KBD430_Shared (J3.16), KBD430_G2xx4 (U3.18)
KSO11: KBD430_F5529 (U1.60), KBD430_Shared (J3.17), KBD430_G2xx4 (U3.19)
KSO12: KBD430_F5529 (U1.15), KBD430_Shared (J3.19), KBD430_G2xx4 (U3.20)
KSO13: KBD430_F5529 (U1.16), KBD430_Shared (J3.20), KBD430_G2xx4 (U3.21)
KSO14: KBD430_F5529 (U1.17), KBD430_Shared (J3.21), KBD430_G2xx4 (U3.22)
PWM1: KBD430_F5529 (U1.25), KBD430_Shared (J5.3)
PWM2: KBD430_F5529 (U1.26), KBD430_Shared (J5.8)
PWM3: KBD430_F5529 (U1.57), KBD430_Shared (J5.6)
PWM4: KBD430_F5529 (U1.58), KBD430_Shared (J5.4)
PWM5: KBD430_F5529 (U1.59), KBD430_Shared (J5.2)
RST/SBWTDIO: KBD430_F5529 (C18.1 R20.1 U1.76), KBD430_Shared (J1.1 J5.9), KBD430_G2xx4 (C34.1 R30.1 U3.5)
SBWTCK: KBD430_F5529 (U1.71), KBD430_Shared (J1.8 R6.2), KBD430_G2xx4 (U3.37)
SPI_CLK: KBD430_F5529 (U1.39), KBD430_Shared (J4.14), KBD430_G2xx4 (U3.12)
SPI_MISO: KBD430_F5529 (U1.38), KBD430_Shared (J5.13)
SPI_MOSI: KBD430_F5529 (U1.37), KBD430_Shared (J5.11)
TCAP1: KBD430_F5529 (U1.23), KBD430_Shared (J5.12)
TCAP2: KBD430_F5529 (U1.24), KBD430_Shared (J5.10)
UART_RX: KBD430_F5529 (U1.41), KBD430_Shared (J4.6), KBD430_G2xx4 (U3.24)
UART_TX: KBD430_F5529 (U1.40), KBD430_Shared (J4.8), KBD430_G2xx4 (U3.23)
VBUS: KBD430_F5529 (5 pins), KBD430_Shared (5 pins)
VCC430: KBD430_F5529 (6 pins), KBD430_Shared (JP2.1), KBD430_G2xx4 (5 pins)

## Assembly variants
001: not fitted FID1 FID2 FID3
